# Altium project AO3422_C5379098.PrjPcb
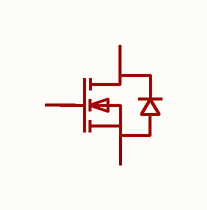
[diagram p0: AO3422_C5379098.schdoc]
1 sheet, 1 parts. Net scope: global (net labels, ports and power ports of the same name join across sheets).

## Sheet AO3422_C5379098.schdoc
size 127 x 101 mm

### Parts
Q?  ao3422_c5379098  [SOT-23-3_L2.9-W1.6-P1.90-LS2.8-BR]  (value not drawn)

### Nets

Not connected (* = marked no-connect by the designer): Q? 1(G) 2(S) 3(D)

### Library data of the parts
Q? = ao3422_c5379098: 数量:1个N沟道;漏源电压(Vdss):55V;连续漏极电流(Id):2A;导通电阻(RDS(on)):120mΩ@10V;耗散功率(Pd):1.56W;阈值电压(Vgs(th)):1.6V;; Manufacturer: MSKSEMI(美森科); ManufacturerPart: AO3422; AddInBom: yes; ModelId: 89cb27a44ab2466697082bb9fd73a7d0; ModelName: SOT-23-3L_L2.9-W1.6-H1.1-LS2.8-P0.95; ModelTransform: 114.173,110.236,0,90,0,0,0,0,0; Number: 1个N沟道; Drain to Source Voltage: 55V; Current - Continuous Drain(Id): 2A; Pd - Power Dissipation: 1.56W; Gate Threshold Voltage (Vgs(th)): 1.6V; Gate Charge(Qg): 9.3nC@10V; Input Capacitance(Ciss): 500pF; Reverse Transfer Capacitance (Crss@Vds): 16pF; Output Capacitance(Coss): 45pF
